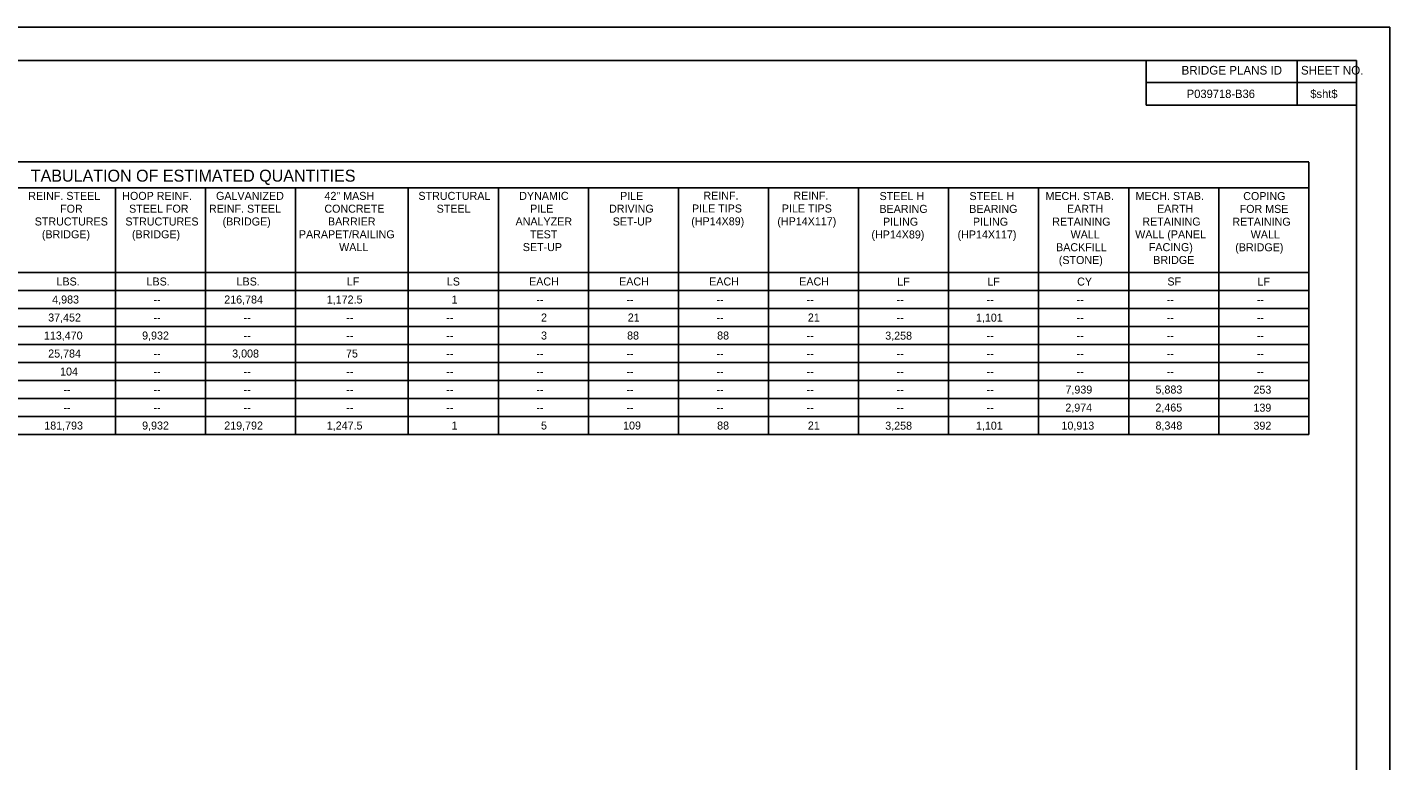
# Model space of a CAD drawing. Extents: x -125.5 to -89.4, y -5.1 to 16.9.
# Drawn here: x -109.96 to -89.53, y 5.93 to 16.93 of the extents above; entities that cross this region are included whole.
import ezdxf

# ---------------------------------------------------------------- set-up
doc = ezdxf.new("R2010")
doc.units = 0
for name, color, linetype in [('BR_BORDER LINES', 7, 'Continuous'), ('BR_TABLE LINES', 7, 'Continuous'), ('BR_TEXT', 7, 'Continuous'), ('Level 31', 7, 'Continuous')]:
    doc.layers.add(name, color=color, linetype=linetype)

msp = doc.modelspace()

# ---------------------------------------------------------------- linework, layer by layer
at = {"layer": 'BR_BORDER LINES'}
for p, q in [((-90.033, 16.434), (-123.699, 16.434)), ((-93.186, 15.767), (-93.186, 16.434)), ((-90.919, 15.767), (-90.919, 16.434)), ((-90.033, -4.566), (-90.033, 16.434)), ((-93.186, 16.104), (-90.033, 16.104)), ((-90.919, 16.104), (-90.033, 16.104)), ((-90.033, 15.767), (-93.186, 15.767))]:
    msp.add_line(p, q, dxfattribs=at)
at = {"layer": 'BR_TABLE LINES'}
for p, q in [((-123.136, 14.914), (-90.746, 14.914)), ((-90.746, 14.913), (-90.746, 10.825)), ((-123.136, 14.524), (-90.746, 14.524)), ((-108.636, 14.524), (-108.636, 10.826)), ((-107.286, 14.524), (-107.286, 10.826)), ((-105.936, 14.524), (-105.936, 10.826)), ((-104.246, 14.524), (-104.246, 10.826)), ((-102.896, 14.524), (-102.896, 10.826)), ((-101.546, 14.524), (-101.546, 10.826)), ((-100.196, 14.524), (-100.196, 10.826)), ((-98.846, 14.524), (-98.846, 10.826)), ((-97.496, 14.521), (-97.496, 10.824)), ((-96.146, 14.522), (-96.146, 10.824)), ((-94.796, 14.523), (-94.796, 10.825)), ((-93.446, 14.523), (-93.446, 10.825)), ((-92.096, 14.522), (-92.096, 10.825)), ((-123.136, 13.256), (-90.746, 13.256)), ((-123.136, 12.986), (-90.746, 12.986)), ((-90.746, 12.716), (-123.136, 12.716)), ((-90.746, 12.446), (-123.136, 12.446)), ((-90.746, 12.176), (-123.136, 12.176)), ((-90.746, 11.906), (-123.136, 11.906)), ((-90.746, 11.636), (-123.136, 11.636)), ((-90.746, 11.366), (-123.136, 11.366)), ((-90.746, 11.096), (-123.136, 11.096)), ((-90.746, 10.826), (-123.136, 10.826))]:
    msp.add_line(p, q, dxfattribs=at)
at = {"layer": 'Level 31'}
msp.add_lwpolyline([(-125.533, -5.066), (-89.533, -5.066), (-89.533, 16.934), (-125.533, 16.934)], close=True, dxfattribs=at)

# ---------------------------------------------------------------- texts
at = {"layer": 'BR_TEXT'}
for s, height, p in [('BRIDGE PLANS ID', 0.13, (-92.654, 16.224)), ('SHEET NO.', 0.13, (-90.864, 16.224)), ('P039718-B36', 0.125, (-92.576, 15.873)), ('$sht$', 0.125, (-90.724, 15.873)), ('TABULATION OF ESTIMATED QUANTITIES', 0.18, (-109.905, 14.618)), ('REINF. STEEL', 0.12, (-109.943, 14.345)), ('HOOP REINF. ', 0.12, (-108.534, 14.345)), ('GALVANIZED ', 0.12, (-107.128, 14.345)), ('42" MASH ', 0.12, (-105.502, 14.345)), ('STRUCTURAL ', 0.12, (-104.094, 14.345)), ('DYNAMIC ', 0.12, (-102.583, 14.345)), ('PILE', 0.12, (-101.071, 14.345)), ('REINF. ', 0.12, (-99.822, 14.348)), ('REINF. ', 0.12, (-98.474, 14.348)), ('STEEL H ', 0.12, (-97.181, 14.342)), ('STEEL H ', 0.12, (-95.833, 14.342)), ('MECH. STAB. ', 0.12, (-94.694, 14.343)), ('MECH. STAB. ', 0.12, (-93.344, 14.344)), ('COPING ', 0.12, (-91.729, 14.342)), (' FOR', 0.12, (-109.51, 14.153)), ('STEEL FOR ', 0.12, (-108.432, 14.153)), ('REINF. STEEL ', 0.12, (-107.234, 14.153)), ('CONCRETE ', 0.12, (-105.504, 14.153)), ('STEEL', 0.12, (-103.821, 14.153)), ('PILE ', 0.12, (-102.419, 14.153)), ('DRIVING', 0.12, (-101.236, 14.153)), ('PILE TIPS ', 0.12, (-99.993, 14.156)), ('PILE TIPS ', 0.12, (-98.646, 14.156)), ('BEARING ', 0.12, (-97.183, 14.15)), ('BEARING ', 0.12, (-95.836, 14.15)), ('EARTH ', 0.12, (-94.371, 14.151)), ('EARTH ', 0.12, (-93.021, 14.152)), ('FOR MSE ', 0.12, (-91.783, 14.15)), (' STRUCTURES ', 0.12, (-109.891, 13.961)), ('(BRIDGE)', 0.12, (-109.739, 13.769)), ('STRUCTURES ', 0.12, (-108.487, 13.961)), ('(BRIDGE)', 0.12, (-108.389, 13.769)), ('(BRIDGE)', 0.12, (-107.03, 13.961)), ('PARAPET/RAILING ', 0.12, (-105.886, 13.769)), ('BARRIER ', 0.12, (-105.45, 13.961)), ('ANALYZER ', 0.12, (-102.638, 13.961)), ('TEST ', 0.12, (-102.422, 13.769)), ('SET-UP', 0.12, (-101.181, 13.961)), ('(HP14X89)', 0.12, (-100.004, 13.964)), ('(HP14X117)', 0.12, (-98.713, 13.964)), ('(HP14X89)', 0.12, (-97.303, 13.766)), ('PILING ', 0.12, (-97.129, 13.958)), ('(HP14X117)', 0.12, (-96.012, 13.766)), ('PILING ', 0.12, (-95.781, 13.958)), ('RETAINING ', 0.12, (-94.592, 13.959)), ('WALL (PANEL ', 0.12, (-93.349, 13.768)), ('RETAINING ', 0.12, (-93.242, 13.96)), ('RETAINING ', 0.12, (-91.892, 13.958)), ('WALL', 0.12, (-105.283, 13.577)), ('SET-UP', 0.12, (-102.529, 13.577)), ('BACKFILL ', 0.12, (-94.535, 13.575)), ('WALL ', 0.12, (-94.317, 13.767)), ('FACING) ', 0.12, (-93.144, 13.576)), ('(BRIDGE)', 0.12, (-91.849, 13.574)), ('WALL ', 0.12, (-91.617, 13.766)), ('(STONE)', 0.12, (-94.494, 13.383)), ('BRIDGE', 0.12, (-93.078, 13.384)), ('LBS.', 0.12, (-109.52, 13.061)), ('LBS.', 0.12, (-108.17, 13.061)), ('LBS.', 0.12, (-106.82, 13.061)), ('LF', 0.12, (-105.167, 13.061)), ('LS', 0.12, (-103.668, 13.061)), ('EACH', 0.12, (-102.435, 13.061)), ('EACH', 0.12, (-101.085, 13.061)), ('EACH', 0.12, (-99.735, 13.061)), ('EACH', 0.12, (-98.385, 13.061)), ('LF', 0.12, (-96.916, 13.059)), ('LF', 0.12, (-95.566, 13.059)), ('CY', 0.12, (-94.219, 13.06)), ('SF', 0.12, (-92.866, 13.061)), ('LF', 0.12, (-91.516, 13.059)), ('4,983', 0.12, (-109.584, 12.791)), ('216,784', 0.12, (-107.005, 12.791)), ('1,172.5', 0.12, (-105.468, 12.791)), ('1', 0.12, (-103.596, 12.791)), ('--', 0.12, (-108.066, 12.791)), ('--', 0.12, (-102.326, 12.791)), ('--', 0.12, (-100.976, 12.791)), ('--', 0.12, (-99.626, 12.791)), ('--', 0.12, (-98.276, 12.791)), ('--', 0.12, (-96.926, 12.789)), ('--', 0.12, (-95.576, 12.789)), ('--', 0.12, (-94.226, 12.79)), ('--', 0.12, (-92.876, 12.791)), ('--', 0.12, (-91.526, 12.789)), ('37,452', 0.12, (-109.644, 12.521)), ('--', 0.12, (-108.066, 12.521)), ('--', 0.12, (-106.716, 12.521)), ('--', 0.12, (-105.177, 12.521)), ('--', 0.12, (-103.676, 12.521)), ('2', 0.12, (-102.256, 12.521)), ('21', 0.12, (-100.956, 12.521)), ('--', 0.12, (-99.626, 12.521)), ('21', 0.12, (-98.256, 12.521)), ('--', 0.12, (-96.926, 12.519)), ('1,101', 0.12, (-95.736, 12.519)), ('--', 0.12, (-94.226, 12.52)), ('--', 0.12, (-92.876, 12.521)), ('--', 0.12, (-91.526, 12.519)), ('113,470', 0.12, (-109.708, 12.251)), ('9,932', 0.12, (-108.236, 12.251)), ('--', 0.12, (-106.716, 12.251)), ('--', 0.12, (-105.177, 12.251)), ('--', 0.12, (-103.676, 12.251)), ('3', 0.12, (-102.256, 12.251)), ('88', 0.12, (-100.966, 12.251)), ('88', 0.12, (-99.616, 12.251)), ('--', 0.12, (-98.276, 12.251)), ('3,258', 0.12, (-97.096, 12.249)), ('--', 0.12, (-95.576, 12.249)), ('--', 0.12, (-94.226, 12.25)), ('--', 0.12, (-92.876, 12.251)), ('--', 0.12, (-91.526, 12.249)), ('25,784', 0.12, (-109.644, 11.981)), ('3,008', 0.12, (-106.886, 11.981)), ('75', 0.12, (-105.18, 11.981)), ('--', 0.12, (-108.066, 11.981)), ('--', 0.12, (-103.676, 11.981)), ('--', 0.12, (-102.326, 11.981)), ('--', 0.12, (-100.976, 11.981)), ('--', 0.12, (-99.626, 11.981)), ('--', 0.12, (-98.276, 11.981)), ('--', 0.12, (-96.926, 11.979)), ('--', 0.12, (-95.576, 11.979)), ('--', 0.12, (-94.226, 11.98)), ('--', 0.12, (-92.876, 11.981)), ('--', 0.12, (-91.526, 11.979)), ('104', 0.12, (-109.466, 11.711)), ('--', 0.12, (-108.066, 11.711)), ('--', 0.12, (-106.716, 11.711)), ('--', 0.12, (-105.177, 11.711)), ('--', 0.12, (-103.676, 11.711)), ('--', 0.12, (-102.326, 11.711)), ('--', 0.12, (-100.976, 11.711)), ('--', 0.12, (-99.626, 11.711)), ('--', 0.12, (-98.276, 11.711)), ('--', 0.12, (-96.926, 11.709)), ('--', 0.12, (-95.576, 11.709)), ('--', 0.12, (-94.226, 11.71)), ('--', 0.12, (-92.876, 11.711)), ('--', 0.12, (-91.526, 11.709)), ('--', 0.12, (-109.416, 11.441)), ('--', 0.12, (-108.066, 11.441)), ('--', 0.12, (-106.716, 11.441)), ('--', 0.12, (-105.177, 11.441)), ('--', 0.12, (-103.676, 11.441)), ('--', 0.12, (-102.326, 11.441)), ('--', 0.12, (-100.976, 11.441)), ('--', 0.12, (-99.626, 11.441)), ('--', 0.12, (-98.276, 11.441)), ('--', 0.12, (-96.926, 11.439)), ('--', 0.12, (-95.576, 11.439)), ('7,939', 0.12, (-94.394, 11.44)), ('5,883', 0.12, (-93.044, 11.441)), ('253', 0.12, (-91.576, 11.439)), ('2,974', 0.12, (-94.396, 11.17)), ('2,465', 0.12, (-93.046, 11.171)), ('139', 0.12, (-91.576, 11.169)), ('--', 0.12, (-109.416, 11.171)), ('--', 0.12, (-108.066, 11.171)), ('--', 0.12, (-106.716, 11.171)), ('--', 0.12, (-105.177, 11.171)), ('--', 0.12, (-103.676, 11.171)), ('--', 0.12, (-102.326, 11.171)), ('--', 0.12, (-100.976, 11.171)), ('--', 0.12, (-99.626, 11.171)), ('--', 0.12, (-98.276, 11.171)), ('--', 0.12, (-96.926, 11.169)), ('--', 0.12, (-95.576, 11.169)), ('181,793', 0.12, (-109.703, 10.901)), ('9,932', 0.12, (-108.236, 10.901)), ('219,792', 0.12, (-107.005, 10.901)), ('1,247.5', 0.12, (-105.468, 10.901)), ('1', 0.12, (-103.596, 10.901)), ('5', 0.12, (-102.256, 10.901)), ('109', 0.12, (-101.026, 10.901)), ('88', 0.12, (-99.616, 10.901)), ('21', 0.12, (-98.256, 10.901)), ('3,258', 0.12, (-97.096, 10.899)), ('1,101', 0.12, (-95.736, 10.899)), ('10,913', 0.12, (-94.454, 10.9)), ('8,348', 0.12, (-93.044, 10.901)), ('392', 0.12, (-91.576, 10.899))]:
    msp.add_text(s, height=height, dxfattribs=at).set_placement(p)

doc.saveas('drawing.dxf')
